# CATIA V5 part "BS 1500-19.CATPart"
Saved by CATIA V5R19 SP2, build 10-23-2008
Part number: BS 1500-19
Bounding box of the stored display mesh (mm): x -31.459 to 31.459, y -31.459 to 31.459, z 0 to 82
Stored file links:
  C:\Users\Bora\Desktop\3D Katı model\BS serisi\BS 1500\BS 1500-19.CATPart
  C:\Program Files\Dassault Systemes\B19\intel_a\reffiles\standard\MetricThickPitch.txt
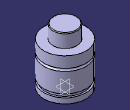
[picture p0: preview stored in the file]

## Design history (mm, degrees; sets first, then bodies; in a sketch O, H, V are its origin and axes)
Body1 (main body)
  Sketch1 on yz-plane, origin (0, 0, 0), H (0, 1, 0), V (0, 0, 1)
    point P1 (31.5, 46)
    point P2 (31.5, 42)
    point P3 (31.5, 46)
    point P7 (18, 81)
    point P9 (18, 81)
    point P14 (31.5, 42)
    arc A1 centre (31.5, 44) radius 2 from (31.5, 46) to (31.5, 42) ccw
    line L1 (31.5, 46) -> (31.5, 62)
    line L2 (31.5, 0) -> (31.5, 8)
    arc A2 centre (17, 81) radius 1 from (18, 81) to (17, 82) ccw
    line L3 (18, 81) -> (18, 62)
    line L4 (29, 13) -> (29, 8)
    line L5 (31.5, 13) -> (31.5, 42)
    line L6 (17, 82) -> (0, 82)
    point P15 (0, 82)
    line L7 (18, 62) -> (31.5, 62)
    line L8 (0, 0) -> (31.5, 0)
    line L9 (29, 13) -> (31.5, 13)
    line L10 (29, 8) -> (31.5, 8)
    coincidence: P15 V, P1 P3, P2 P14, P7 P9
    tangency: L6 A2
    horizontal: L7 H, L8 H, L9 H, L10 H
  Shaft1: profile Sketch1, axis Sketch1.V, angle 360
  Sketch2 on face of Shaft1 from Sketch1.L8, origin (0, 0, 0), H (1, 0, 0), V (0, -1, 0)
    point P1 (10, 0)
    distance P1 V = 10
  Hole1: placed by Sketch2, at (10, 0, 0) direction (0, 0, 1), diameter 6.647, depth 5, threaded "M8", thread diameter 8, thread depth 5, pitch 1.25
  CircPattern1: of Hole1, instances 2, angular step 180, axis from xy-plane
